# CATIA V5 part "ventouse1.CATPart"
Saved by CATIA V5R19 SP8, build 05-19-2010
Part number: 1
Definition: NONE
Nomenclature: 1
Source: Unknown
Description: PART-1-DESC
Bounding box of the stored display mesh (mm): x -26.5 to 26.5, y 0 to 33, z -26.5 to 26.5
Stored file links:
  G:\EU_thinkMotion\CFAO_2010\SIL_groupe1\SIL_groupe1\A reprendre\fbruguiere\fbruguiere\fbruguiere\ventouse1.CATPart
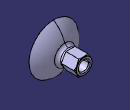
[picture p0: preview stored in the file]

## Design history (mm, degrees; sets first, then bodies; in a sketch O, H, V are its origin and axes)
Set1
  Sketch1 on face of Solid1, origin (0, 0, 0), H (1, 0, 0), V (0, 0, 1)
Body1 "1" (main body)
  Solid1: solid without history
